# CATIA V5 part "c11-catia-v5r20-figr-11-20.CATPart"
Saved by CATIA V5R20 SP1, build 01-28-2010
Part number: Part1
Bounding box of the stored display mesh (mm): x -89.703 to 75.958, y -127.286 to 108.862, z -26.487 to 19.815
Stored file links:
  D:\v5_r20\psrt_files_downloaded\c11\c11-catia-v5r20-figr-11-20.CATPart
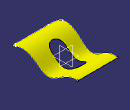
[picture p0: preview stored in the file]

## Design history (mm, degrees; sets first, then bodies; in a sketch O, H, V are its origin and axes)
Set1
  Extrude1: Element1 Sketch3, Lim1 86, Lim2 94, Direction yz-plane
  Sketch1 on xy-plane, origin (0, 0, 0), H (1, 0, 0), V (0, 1, 0)
    line L1 (64.3059, 108.8616) -> (75.9293, -106.0218)
    arc A1 centre (55.7837, -107.1115) radius 20.175 from (75.9293, -106.0218) to (55.7837, -127.2865) cw
    line L2 (55.7837, -127.2865) -> (-64.7868, -127.2865)
    arc A2 centre (-64.7868, -102.3613) radius 24.9252 from (-64.7868, -127.2865) to (-89.6873, -101.2501) cw
    line L3 (-89.6873, -101.2501) -> (-80.3115, 108.8616)
    line L4 (-80.3115, 108.8616) -> (64.3059, 108.8616)
    tangency: A1 L1, A2 L2, A2 L3, A1 L2
    horizontal: L2 H, L4 H
  Extrude2: Element1 Sketch1, Lim1 86, Lim2 94, Direction xy-plane
  Split1: ToCut Extrude1, Cutting Extrude2
  Sketch2 on xy-plane, origin (0, 0, 0), H (1, 0, 0), V (0, 1, 0)
    construction line L1 (-11.3849, 28.4134) -> (-11.3849, -36.9379)
    line L2 (12.8382, 28.4134) -> (12.8382, -36.9379)
    line L3 (-35.608, -36.9379) -> (-35.608, 28.4134)
    arc A1 centre (-11.3849, -36.9379) radius 24.2231 from (12.8382, -36.9379) to (-35.608, -36.9379) cw
    arc A2 centre (-11.3849, 28.4134) radius 24.2231 from (-35.608, 28.4134) to (12.8382, 28.4134) cw
    vertical: L1 V
    tangency: A1 L2, A2 L2, A1 L3, A2 L3
    parallelism: L1 L2
  Extrude3: Element1 Sketch2, Lim1 86, Lim2 94, Direction xy-plane
  Split2: ToCut Split1, Cutting Extrude3
  Boundary1: Boundary edge of Split2, Support Split2
Body1 (main body)
  Sketch3 on yz-plane, origin (0, 0, 0), H (0, 1, 0), V (0, 0, 1)
    spline S1 through (-130.9721, 0) (-85.5087, 19.8151) (-38.0512, 0) (0, -25.6483) (60.0541, -1.7202) (134.7951, -4.3868)
    point P1 (-130.9721, 0)
    point P2 (-38.0512, 0)
    point P3 (0, -25.6483)
    coincidence: P1 H, P2 H, P3 V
